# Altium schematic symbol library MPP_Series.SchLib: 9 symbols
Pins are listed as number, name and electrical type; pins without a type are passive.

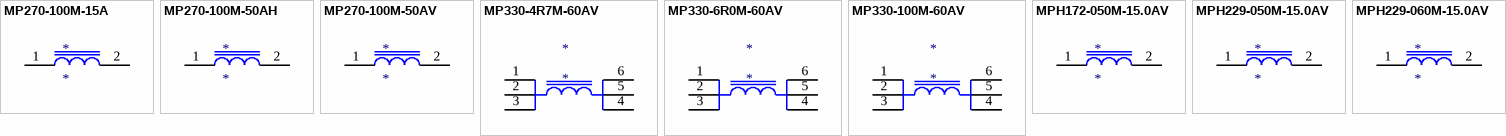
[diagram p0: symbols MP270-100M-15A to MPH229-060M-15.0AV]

## MP270-100M-15A
designator *
POWER INDUCTOR 15 A, 10 uH, 4 mOhms, OD 32 mm, HT 17.27 mm; Manufacturer #1: CWS; Current: 15 A; DCR: 4 mOhms; Inductance: 10 uH; OD: 32 mm
footprint MP270-100M-15A
pins: 1, 2

## MP270-100M-50AH
designator *
POWER INDUCTOR 50 A, 10 uH, 1.5 mOhms, OD 38.1 mm, HT 20.32 mm; Manufacturer #1: CWS; Current: 50 A; Inductance: 10 uH; OD: 38.1 mm
footprint MP270-100M-50AH
pins: 1, 2

## MP270-100M-50AV
designator *
POWER INDUCTOR 50 A, 10 uH, 1.5 mOhms, OD 34.29 mm, HT 20.32 mm; Manufacturer #1: CWS; Current: 50 A; Inductance: 10 uH
footprint MP270-100M-50AV
pins: 1, 2

## MP330-4R7M-60AV
designator *
POWER INDUCTOR 60 A, 4.7 uH, 1 mOhms, OD 41.91 mm, HT 22.1 mm; Manufacturer #1: CWS; Current: 60 A; DCR: 1 mOhms; Inductance: 4.7 uH
footprint MP330-4R7M-60AV
pins: 1, 2, 3, 4, 5, 6

## MP330-6R0M-60AV
designator *
POWER INDUCTOR 60 A, 6 uH, 1 mOhms, OD 41.91 mm, HT 22.1 mm; Manufacturer #1: CWS; Current: 60 A; DCR: 1 mOhms; Inductance: 6 uH
footprint MP330-6R0M-60AV
pins: 1, 2, 3, 4, 5, 6

## MP330-100M-60AV
designator *
POWER INDUCTOR 60 A, 10 uH, 1 mOhms, OD 41.91 mm, HT 22.1 mm; Manufacturer #1: CWS; Current: 60 A; DCR: 1 mOhms; Inductance: 10 uH
footprint MP330-100M-60AV
pins: 1, 2, 3, 4, 5, 6

## MPH172-050M-15.0AV
designator *
POWER INDUCTOR 15 A, 5 uH, 6 mOhms, OD 25.4 mm, HT 10.41 mm; Manufacturer #1: CWS; Current: 15 A; DCR: 6 mOhms; Inductance: 5 uH; OD: 25.4 mm
footprint MPH172-050M-15.0AV
pins: 1, 2

## MPH229-050M-15.0AV
designator *
POWER INDUCTOR 15 A, 5 uH, 8.3 mOhms, OD 43.18 mm, HT 12.95 mm; Manufacturer #1: CWS; Current: 15 A; Inductance: 5 uH
footprint MPH229-050M-15.0AV
pins: 1, 2

## MPH229-060M-15.0AV
designator *
POWER INDUCTOR 15 A, 6 uH, 6.2 mOhms, OD 27.43 mm, HT 12.45 mm; Manufacturer #1: CWS; Current: 15 A; Inductance: 6 uH
footprint MPH229-060M-15.0AV
pins: 1, 2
